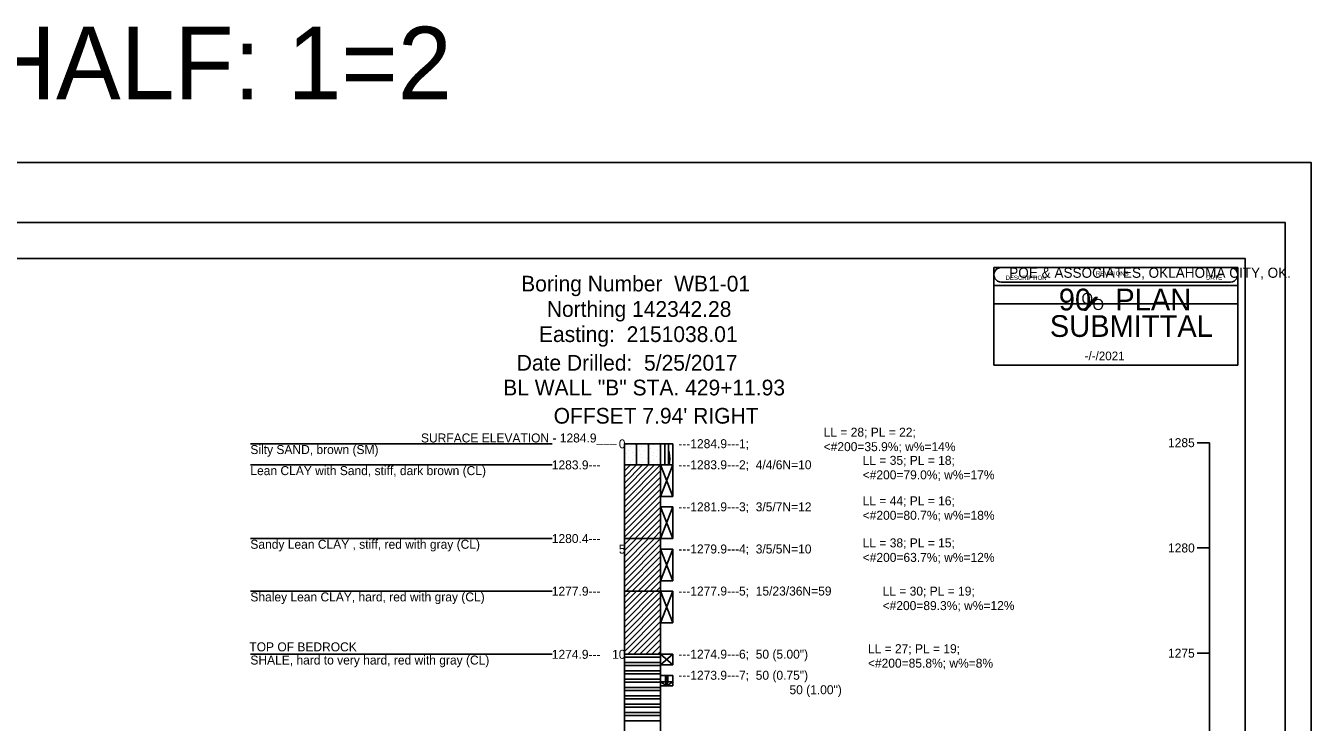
# Model space of a CAD drawing. Extents: x 7 to 126, y 24 to 56.
# Drawn here: x 24.87 to 42.62, y 46.24 to 55.86 of the extents above; entities that cross this region are included whole.
import ezdxf

# ---------------------------------------------------------------- set-up
doc = ezdxf.new("R2010")
doc.units = 0
for name, color, linetype in [('S', 7, 'Continuous'), ('SHT_Plot_Shape_Full', 7, 'Continuous'), ('SHT_Plot_Shape_Half', 7, 'Continuous'), ('SHT_Sheet_Border', 7, 'Continuous'), ('SHT_Stamp_90_Submit', 7, 'Continuous'), ('SHT_Stamp_Rev_Block', 7, 'Continuous')]:
    doc.layers.add(name, color=color, linetype=linetype)

# ---------------------------------------------------------------- blocks, each defined once
blk = doc.blocks.new('POINT_DISPLAY')
blk.add_line((0, 0), (0, 0))

msp = doc.modelspace()

# ---------------------------------------------------------------- linework, layer by layer
msp.add_line((41.217, 37.021), (41.217, 50.103))
for points in [[(27.975, 50.087), (32.142, 50.087)], [(33.14, 50.087), (33.14, 38.168)], [(33.14, 50.087), (33.64, 50.087)], [(33.307, 49.796), (33.307, 50.087)], [(33.474, 49.796), (33.474, 50.087)], [(33.64, 50.087), (33.807, 50.087)], [(33.64, 50.087), (33.64, 38.168)], [(33.807, 49.796), (33.807, 50.087)], [(41.217, 50.103), (41.05, 50.103)], [(27.975, 49.796), (32.142, 49.796)], [(33.14, 49.796), (33.64, 49.796)], [(33.14, 49.713), (33.224, 49.796)], [(33.14, 49.629), (33.307, 49.796)], [(33.14, 49.546), (33.39, 49.796)], [(33.14, 49.463), (33.474, 49.796)], [(33.14, 49.379), (33.557, 49.796)], [(33.14, 49.296), (33.64, 49.796)], [(33.14, 49.213), (33.64, 49.713)], [(33.64, 49.796), (33.807, 49.796)], [(33.64, 49.796), (33.807, 49.36)], [(33.64, 49.36), (33.807, 49.796)], [(33.64, 49.796), (33.807, 49.796)], [(33.807, 49.36), (33.807, 49.796)], [(33.14, 49.129), (33.64, 49.629)], [(33.14, 49.046), (33.64, 49.546)], [(33.14, 48.963), (33.64, 49.463)], [(33.14, 48.879), (33.64, 49.379)], [(33.64, 49.36), (33.807, 49.36)], [(33.14, 48.796), (33.64, 49.296)], [(33.206, 48.779), (33.64, 49.213)], [(33.64, 49.215), (33.807, 48.779)], [(33.64, 48.779), (33.807, 49.215)], [(33.64, 49.215), (33.807, 49.215)], [(33.807, 48.779), (33.807, 49.215)], [(33.29, 48.779), (33.64, 49.129)], [(33.373, 48.779), (33.64, 49.046)], [(33.456, 48.779), (33.64, 48.963)], [(33.54, 48.779), (33.64, 48.879)], [(27.975, 48.779), (32.142, 48.779)], [(33.14, 48.779), (33.64, 48.779)], [(33.14, 48.695), (33.224, 48.779)], [(33.14, 48.612), (33.307, 48.779)], [(33.14, 48.529), (33.39, 48.779)], [(33.14, 48.445), (33.474, 48.779)], [(33.14, 48.362), (33.557, 48.779)], [(33.14, 48.279), (33.64, 48.779)], [(33.14, 48.195), (33.64, 48.695)], [(33.623, 48.779), (33.64, 48.796)], [(33.64, 48.779), (33.807, 48.779)], [(41.217, 48.649), (41.05, 48.649)], [(33.14, 48.112), (33.64, 48.612)], [(33.164, 48.052), (33.64, 48.529)], [(33.64, 48.633), (33.807, 48.197)], [(33.64, 48.197), (33.807, 48.633)], [(33.64, 48.633), (33.807, 48.633)], [(33.807, 48.197), (33.807, 48.633)], [(33.247, 48.052), (33.64, 48.445)], [(33.33, 48.052), (33.64, 48.362)], [(33.414, 48.052), (33.64, 48.279)], [(33.497, 48.052), (33.64, 48.195)], [(33.58, 48.052), (33.64, 48.112)], [(33.64, 48.197), (33.807, 48.197)], [(27.975, 48.052), (32.142, 48.052)], [(33.14, 48.052), (33.64, 48.052)], [(33.14, 47.969), (33.224, 48.052)], [(33.14, 47.885), (33.307, 48.052)], [(33.14, 47.802), (33.39, 48.052)], [(33.14, 47.719), (33.474, 48.052)], [(33.14, 47.635), (33.557, 48.052)], [(33.14, 47.552), (33.64, 48.052)], [(33.14, 47.469), (33.64, 47.969)], [(33.64, 48.052), (33.807, 47.616)], [(33.64, 47.616), (33.807, 48.052)], [(33.64, 48.052), (33.807, 48.052)], [(33.807, 47.616), (33.807, 48.052)], [(33.14, 47.385), (33.64, 47.885)], [(33.14, 47.302), (33.64, 47.802)], [(33.14, 47.219), (33.64, 47.719)], [(33.185, 47.18), (33.64, 47.635)], [(33.64, 47.616), (33.807, 47.616)], [(33.268, 47.18), (33.64, 47.552)], [(33.352, 47.18), (33.64, 47.469)], [(33.435, 47.18), (33.64, 47.385)], [(33.518, 47.18), (33.64, 47.302)], [(27.975, 47.18), (32.142, 47.18)], [(33.14, 47.18), (33.64, 47.18)], [(33.14, 47.18), (33.64, 47.18)], [(33.14, 47.14), (33.64, 47.14)], [(33.14, 47.065), (33.64, 47.065)], [(33.602, 47.18), (33.64, 47.219)], [(33.64, 47.18), (33.807, 47.034)], [(33.64, 47.034), (33.807, 47.18)], [(33.64, 47.18), (33.807, 47.18)], [(33.807, 47.034), (33.807, 47.18)], [(41.217, 47.196), (41.05, 47.196)], [(33.14, 47.026), (33.64, 47.026)], [(33.14, 46.95), (33.64, 46.95)], [(33.14, 46.911), (33.64, 46.911)], [(33.64, 47.034), (33.807, 47.034)], [(33.64, 46.889), (33.807, 46.889)], [(33.807, 46.744), (33.807, 46.889)], [(33.14, 46.835), (33.64, 46.835)], [(33.14, 46.796), (33.64, 46.796)], [(33.14, 46.72), (33.64, 46.72)], [(33.64, 46.744), (33.807, 46.744)], [(33.14, 46.681), (33.64, 46.681)], [(33.14, 46.606), (33.64, 46.606)], [(33.14, 46.566), (33.64, 46.566)], [(33.14, 46.491), (33.64, 46.491)], [(33.14, 46.451), (33.64, 46.451)], [(33.14, 46.376), (33.64, 46.376)], [(33.14, 46.337), (33.64, 46.337)], [(33.14, 46.261), (33.64, 46.261)]]:
    msp.add_lwpolyline(points)
for points in [[(33.699, 50.087), (33.699, 49.796), (33.749, 49.796), (33.749, 50.087)], [(33.763, 49.92), (33.757, 49.962), (33.749, 50.002), (33.763, 49.92)], [(33.749, 50.002), (33.749, 49.796), (33.763, 49.92), (33.749, 50.002)], [(33.749, 49.796), (33.763, 49.837), (33.763, 49.92), (33.749, 49.796)], [(33.763, 49.837), (33.765, 49.878), (33.763, 49.92), (33.763, 49.837)], [(33.749, 49.796), (33.757, 49.796), (33.763, 49.837), (33.749, 49.796)], [(33.707, 46.802), (33.74, 46.802), (33.74, 46.889), (33.707, 46.802)], [(33.707, 46.802), (33.74, 46.889), (33.707, 46.889), (33.707, 46.802)], [(33.707, 46.802), (33.64, 46.802), (33.724, 46.744), (33.707, 46.802)], [(33.707, 46.802), (33.724, 46.744), (33.74, 46.802), (33.707, 46.802)], [(33.724, 46.744), (33.807, 46.802), (33.74, 46.802), (33.724, 46.744)]]:
    msp.add_lwpolyline(points, close=True)
at = {"layer": 'SHT_Plot_Shape_Full'}
msp.add_lwpolyline([(6.624, 53.971), (42.624, 53.971), (42.624, 29.971), (6.624, 29.971)], close=True, dxfattribs=at)
at = {"layer": 'SHT_Plot_Shape_Half'}
msp.add_lwpolyline([(8.262, 53.146), (42.262, 53.146), (42.262, 31.146), (8.262, 31.146)], close=True, dxfattribs=at)
at = {"layer": 'SHT_Sheet_Border'}
msp.add_lwpolyline([(10.212, 52.646), (41.712, 52.646), (41.712, 31.646), (10.212, 31.646)], close=True, dxfattribs=at)
at = {"layer": 'SHT_Stamp_90_Submit'}
for p, q in [((38.343, 52.522), (41.509, 52.522)), ((38.243, 52.272), (41.609, 52.272)), ((38.243, 51.173), (38.243, 52.272)), ((38.343, 52.322), (41.509, 52.322)), ((41.609, 51.173), (41.609, 52.272)), ((39.486, 51.934), (39.641, 52.107)), ((39.504, 51.934), (39.659, 52.107)), ((39.509, 51.934), (39.664, 52.107)), ((39.516, 51.934), (39.672, 52.107)), ((39.641, 52.107), (39.672, 52.107)), ((39.486, 51.934), (39.516, 51.934)), ((38.243, 51.173), (41.609, 51.173))]:
    msp.add_line(p, q, dxfattribs=at)
for centre, start, end in [((38.343, 52.422), 89.9952, 270), ((41.509, 52.422), 270, 90.0048)]:
    msp.add_arc(centre, 0.1, start, end, dxfattribs=at)
at = {"layer": 'SHT_Stamp_Rev_Block'}
for p, q in [((38.243, 52.522), (38.243, 52.022)), ((41.609, 52.522), (38.243, 52.522)), ((41.609, 52.022), (41.609, 52.522)), ((41.609, 52.272), (38.243, 52.272)), ((41.609, 52.022), (38.243, 52.022))]:
    msp.add_line(p, q, dxfattribs=at)

# ---------------------------------------------------------------- block references
at = {"xscale": 0.01, "yscale": 0.01}
for p in [(33.17, 50.074), (33.295, 50.074), (33.459, 50.062), (33.545, 50.074), (33.145, 50.024), (33.17, 49.949), (33.195, 49.999), (33.195, 49.899), (33.22, 50.049), (33.245, 49.974), (33.295, 49.924), (33.312, 50.027), (33.345, 49.999), (33.357, 49.942), (33.37, 50.049), (33.37, 49.899), (33.42, 49.999), (33.458, 49.886), (33.47, 49.949), (33.495, 50.024), (33.526, 49.921), (33.545, 49.974), (33.587, 49.917), (33.595, 49.999), (33.62, 50.049), (33.636, 49.924), (33.145, 49.849), (33.146, 49.713), (33.179, 49.779), (33.22, 49.824), (33.245, 49.874), (33.246, 49.746), (33.27, 49.799), (33.308, 49.866), (33.346, 49.779), (33.347, 49.814), (33.369, 49.716), (33.395, 49.824), (33.445, 49.799), (33.446, 49.746), (33.495, 49.849), (33.545, 49.874), (33.566, 49.763), (33.595, 49.824), (33.613, 49.713), (33.62, 49.874), (33.179, 49.613), (33.213, 49.679), (33.213, 49.546), (33.279, 49.646), (33.346, 49.579), (33.413, 49.679), (33.43, 49.604), (33.446, 49.546), (33.513, 49.679), (33.564, 49.528), (33.579, 49.613), (33.146, 49.479), (33.246, 49.446), (33.279, 49.513), (33.313, 49.413), (33.365, 49.502), (33.379, 49.379), (33.416, 49.432), (33.479, 49.446), (33.546, 49.413), (33.613, 49.479), (33.146, 49.279), (33.179, 49.213), (33.213, 49.346), (33.246, 49.246), (33.346, 49.313), (33.379, 49.179), (33.413, 49.246), (33.458, 49.346), (33.513, 49.279), (33.579, 49.346), (33.579, 49.213), (33.146, 49.046), (33.179, 49.113), (33.213, 49.013), (33.246, 49.079), (33.346, 49.113), (33.369, 49.049), (33.413, 49.013), (33.446, 49.079), (33.479, 49.146), (33.513, 49.013), (33.566, 49.096), (33.613, 49.046), (33.179, 48.946), (33.213, 48.879), (33.279, 48.979), (33.279, 48.846), (33.346, 48.913), (33.365, 48.835), (33.43, 48.937), (33.446, 48.879), (33.564, 48.861), (33.579, 48.946), (33.146, 48.813), (33.146, 48.695), (33.179, 48.762), (33.213, 48.662), (33.246, 48.779), (33.246, 48.729), (33.346, 48.762), (33.369, 48.698), (33.413, 48.662), (33.446, 48.729), (33.479, 48.779), (33.513, 48.662), (33.566, 48.745), (33.613, 48.813), (33.613, 48.695), (33.179, 48.595), (33.213, 48.529), (33.279, 48.629), (33.279, 48.495), (33.346, 48.562), (33.365, 48.485), (33.43, 48.586), (33.446, 48.529), (33.564, 48.51), (33.579, 48.595), (33.146, 48.462), (33.213, 48.329), (33.246, 48.429), (33.313, 48.395), (33.346, 48.295), (33.379, 48.362), (33.416, 48.415), (33.458, 48.329), (33.479, 48.429), (33.546, 48.395), (33.579, 48.329), (33.613, 48.462), (33.146, 48.262), (33.179, 48.195), (33.246, 48.229), (33.379, 48.162), (33.413, 48.229), (33.479, 48.129), (33.513, 48.262), (33.579, 48.195), (33.179, 48.095), (33.246, 48.062), (33.346, 48.095), (33.446, 48.062), (33.566, 48.079)]:
    msp.add_blockref('POINT_DISPLAY', p, dxfattribs=at)

# ---------------------------------------------------------------- texts
for s, height, p in [('Boring Number  WB1-01', 0.217, (31.714, 52.191)), ('Northing 142342.28', 0.217, (32.068, 51.841)), ('Easting:  2151038.01', 0.217, (31.96, 51.493)), ('Date Drilled:  5/25/2017', 0.217, (31.653, 51.098)), ('BL WALL "B" STA. 429+11.93', 0.217, (31.466, 50.756)), ("OFFSET 7.94' RIGHT", 0.217, (32.163, 50.366)), ('LL = 28; PL = 22;', 0.124, (35.891, 50.186)), ('Silty SAND, brown (SM)', 0.124, (27.975, 49.946)), ('SURFACE ELEVATION - 1284.9___', 0.124, (30.331, 50.106)), ('0', 0.124, (33.062, 50.025)), ('---1284.9---1;', 0.124, (33.884, 50.027)), ('<#200=35.9%; w%=14%', 0.124, (35.891, 49.986)), ('1285', 0.124, (40.646, 50.041)), ('LL = 35; PL = 18;', 0.124, (36.43, 49.797)), ('Lean CLAY with Sand, stiff, dark brown (CL)', 0.124, (27.975, 49.655)), ('1283.9---', 0.124, (32.137, 49.734)), ('---1283.9---2;  4/4/6N=10', 0.124, (33.884, 49.736)), ('<#200=79.0%; w%=17%', 0.124, (36.43, 49.597)), ('LL = 44; PL = 16;', 0.124, (36.43, 49.238)), ('---1281.9---3;  3/5/7N=12', 0.124, (33.884, 49.155)), ('<#200=80.7%; w%=18%', 0.124, (36.43, 49.038)), ('1280.4---', 0.124, (32.137, 48.717)), ('Sandy Lean CLAY , stiff, red with gray (CL)', 0.124, (27.975, 48.638)), ('5', 0.124, (33.062, 48.571)), ('---1279.9---4;  3/5/5N=10', 0.124, (33.884, 48.573)), ('LL = 38; PL = 15;', 0.124, (36.43, 48.657)), ('1280', 0.124, (40.646, 48.587)), ('<#200=63.7%; w%=12%', 0.124, (36.43, 48.457)), ('1277.9---', 0.124, (32.137, 47.99)), ('---1277.9---5;  15/23/36N=59', 0.124, (33.884, 47.992)), ('LL = 30; PL = 19;', 0.124, (36.705, 47.991)), ('Shaley Lean CLAY, hard, red with gray (CL)', 0.124, (27.975, 47.911)), ('<#200=89.3%; w%=12%', 0.124, (36.705, 47.791)), ('TOP OF BEDROCK', 0.124, (27.961, 47.221)), ('1274.9---', 0.124, (32.137, 47.118)), ('10', 0.124, (32.97, 47.118)), ('---1274.9---6;  50 (5.00")', 0.124, (33.884, 47.12)), ('LL = 27; PL = 19;', 0.124, (36.502, 47.196)), ('1275', 0.124, (40.646, 47.134)), ('SHALE, hard to very hard, red with gray (CL)', 0.124, (27.975, 47.039)), ('<#200=85.8%; w%=8%', 0.124, (36.502, 46.996)), ('---1273.9---7;  50 (0.75")', 0.124, (33.884, 46.829)), ('50 (1.00")', 0.124, (35.419, 46.629))]:
    msp.add_text(s, height=height).set_placement(p)
at = {"layer": 'S'}
msp.add_text('FULL: 1=1   HALF: 1=2', height=1, dxfattribs=at).set_placement((16.93, 54.847))
at = {"layer": 'SHT_Stamp_90_Submit'}
for s, height, p in [('POE & ASSOCIATES, OKLAHOMA CITY, OK.', 0.14, (38.453, 52.38)), ('90   PLAN', 0.3, (39.138, 51.93)), ('O', 0.153, (39.451, 52.019)), ('O', 0.153, (39.603, 51.935)), ('SUBMITTAL', 0.3, (39.014, 51.564)), ('-/-/2021', 0.12, (39.494, 51.241))]:
    msp.add_text(s, height=height, dxfattribs=at).set_placement(p)
at = {"layer": 'SHT_Stamp_Rev_Block'}
for s, height, p in [('DESCRIPTION', 0.05999, (38.403, 52.351)), ('REVISIONS', 0.06, (39.651, 52.41)), ('DATE', 0.06, (41.172, 52.355))]:
    msp.add_text(s, height=height, dxfattribs=at).set_placement(p)

doc.saveas('drawing.dxf')
